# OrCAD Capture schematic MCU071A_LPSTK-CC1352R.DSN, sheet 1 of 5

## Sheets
1 1_RF: size A3; title: LPSTK-CC1352R1; rev: A; company: Texas Instruments
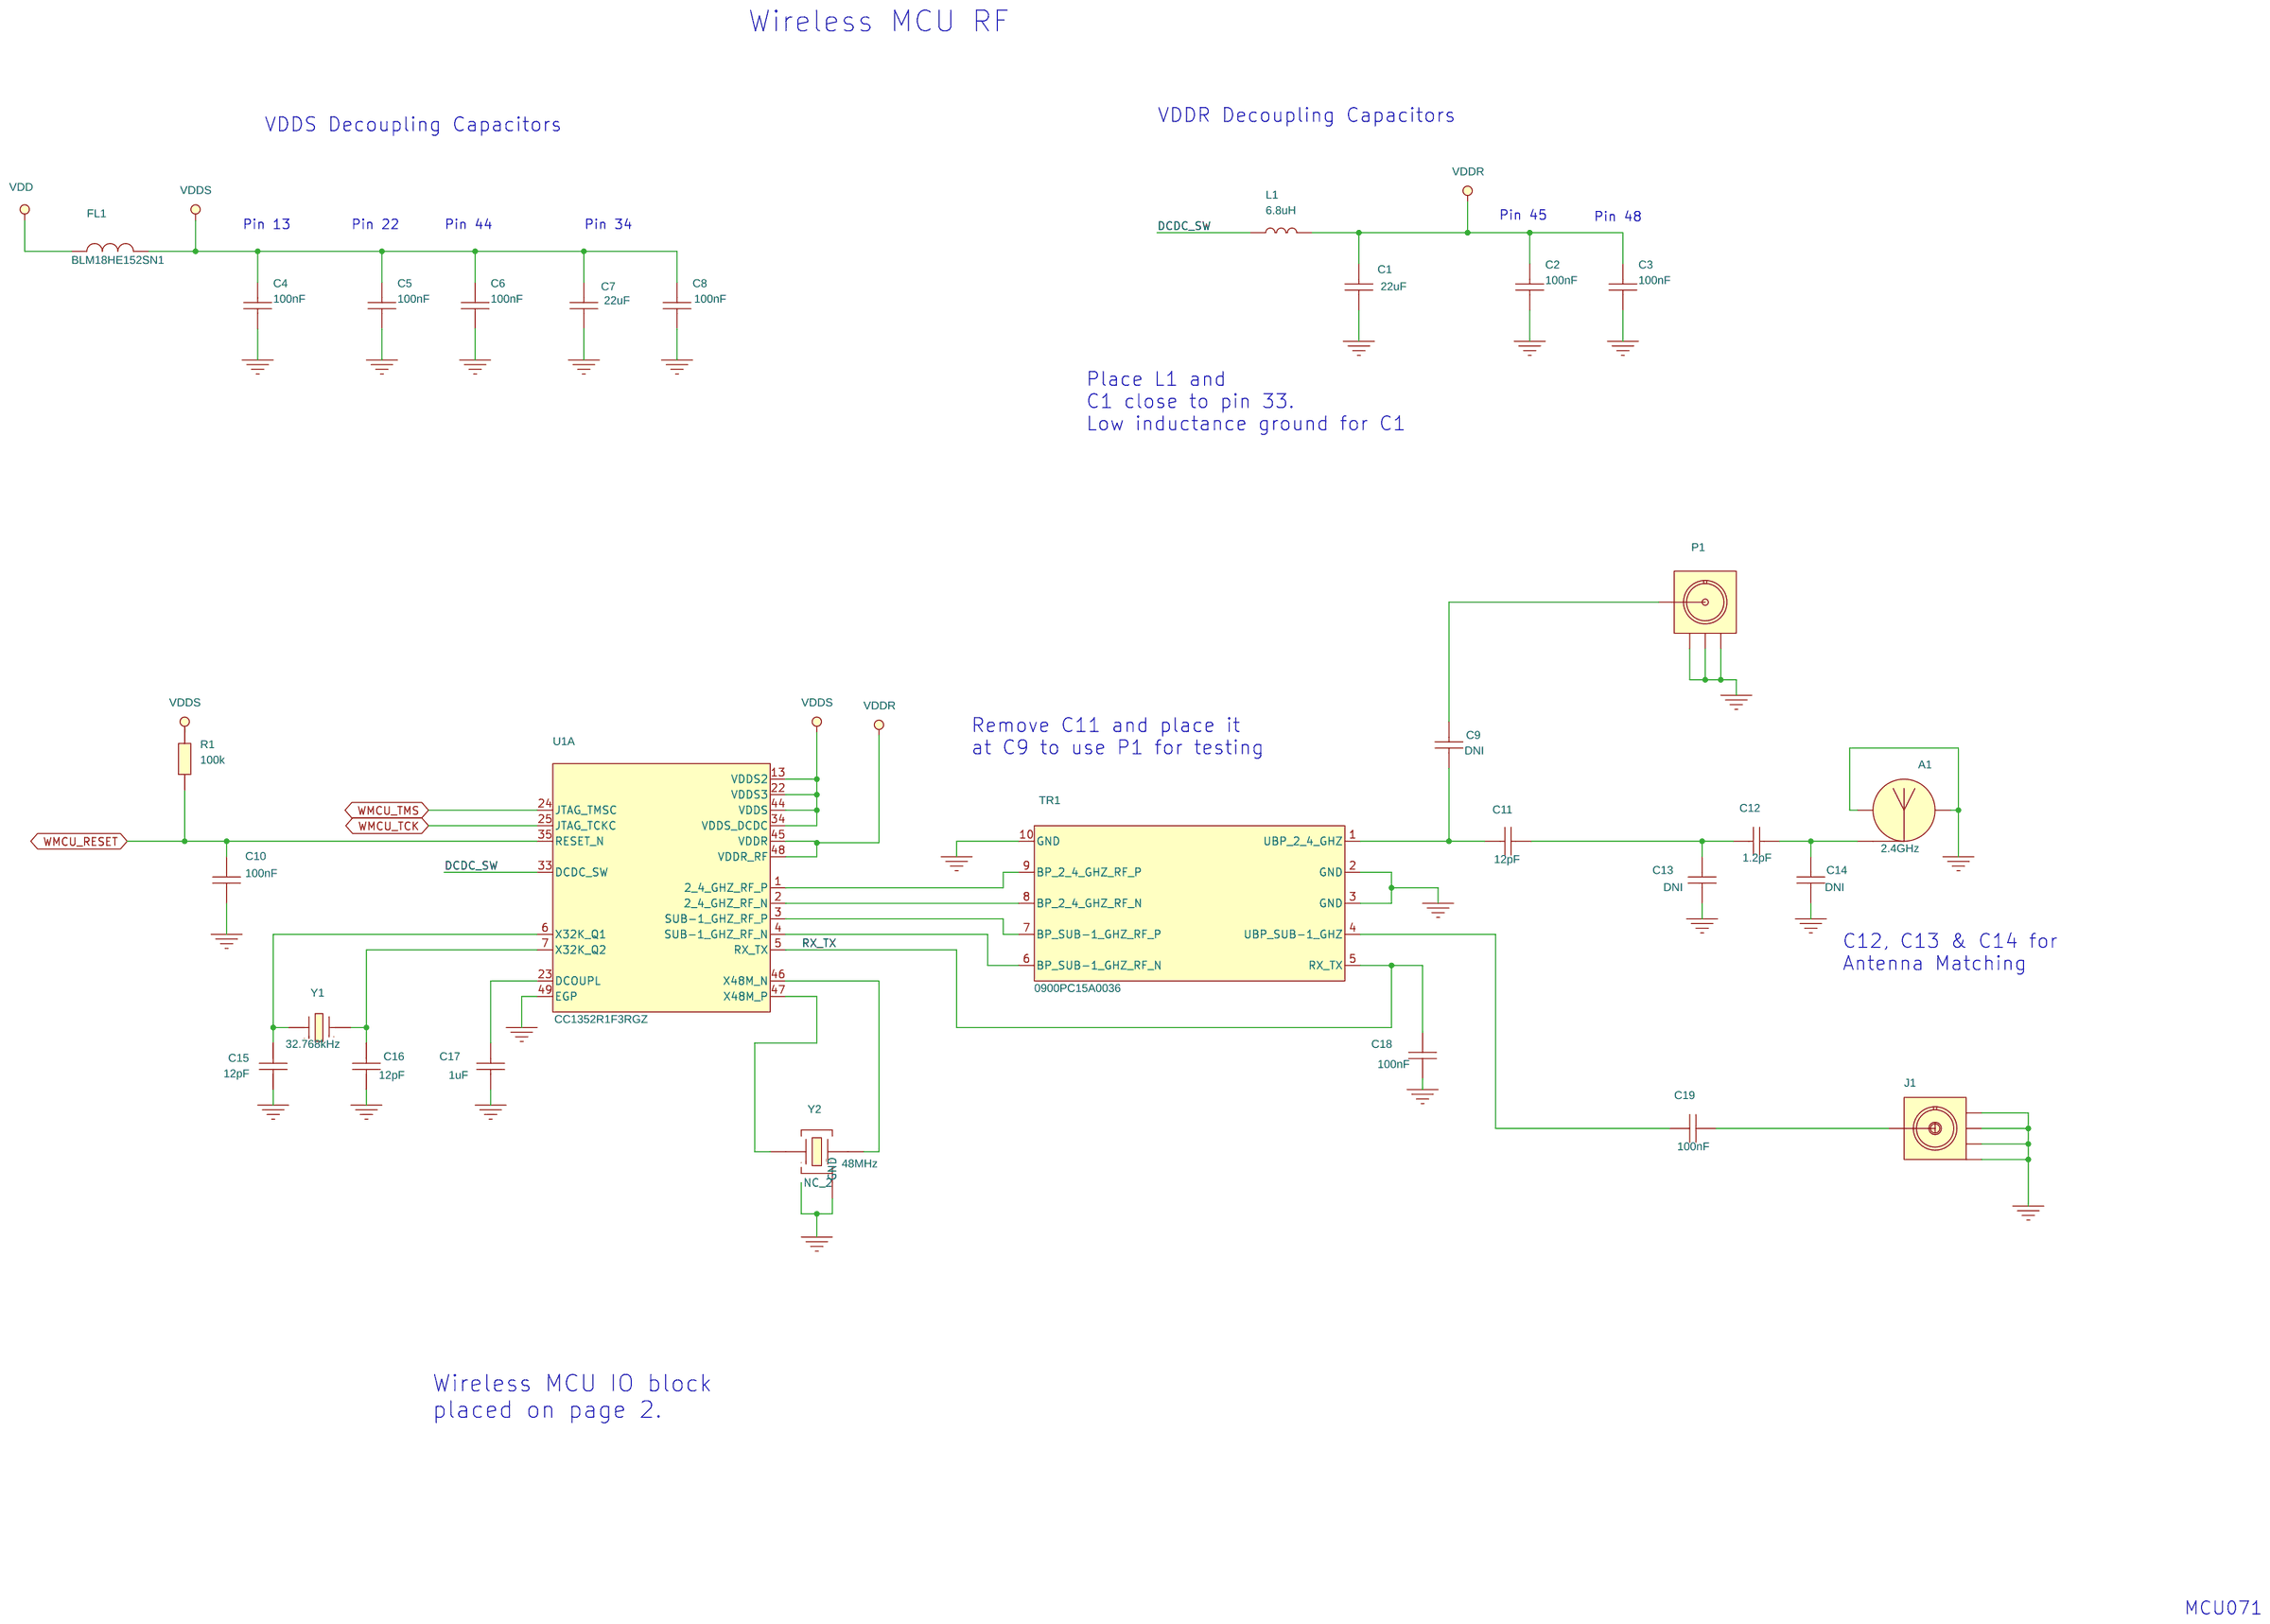
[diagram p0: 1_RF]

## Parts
A1  2.4GHz  [ANTENNA_DN007N]
C1  22uF  [CAPC1608X100A2N]
C2  100nF  [CAPC1005X60A2N]
C3  100nF  [CAPC1005X60A2N]
C4  100nF  [CAPC1005X60A2N]
C5  100nF  [CAPC1005X60A2N]
C6  100nF  [CAPC1005X60A2N]
C7  22uF  [CAPC1608X100A2N]
C8  100nF  [CAPC1005X60A2N]
C9  DNI  [CAPC0603X35B2N]
C10  100nF  [CAPC1005X60A2N]
C11  12pF  [CAPC0603X35B2N]
C12  1.2pF  [CAPC0603X35B2N]
C13  DNI  [CAPC0603X35B2N]
C14  DNI  [CAPC0603X35B2N]
C15  12pF  [CAPC1005X60A2N]
C16  12pF  [CAPC1005X60A2N]
C17  1uF  [CAPC1005X60A2N]
C18  100nF  [CAPC0603X35B2N]
C19  100nF  [CAPC0603X35B2N]
FL1  BLM18HE152SN1  [FIL_BLM18HE152SN1DN]
J1  SLE-100010011  [DONGGUAN_SLE100010011_A2N]
L1  6.8uH  [INDC2012X150A2N]
P1  MM5829-2700  [MURATA_MM58292700RJ4_A2N]
R1  100k  [RESC1005X40B2N]
TR1  0900PC15A0036  [XFMR_IPC1352_A2N]
U1  CC1352R1F3RGZ  [QFNFC50P700X700X100-49A2N]  (sections A,B)
Y1  32.768kHz  [XTAL_FC135_A2N]
Y2  48MHz  [XTAL_XRCMD_A2N]

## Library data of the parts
A1 = ANTENNA_DN007_0: ANTENNA, NON COMPONENT, 2.4GHz INVERTED F ANTENNA, NOT APPLY; Additional Datasheet URL: N/A; CLASS: DISCRETE; Country of Origin: Missing Info; Datasheet URL: www.ti.com; Exclusive for Customers: TEXAS INSTRUMENTS NORWAY; FPLIST: ANTENNA_DN007N,ANTENNA_DN007AN; Mass: N/A; Maximum Operating Temperature: +85DEGC; Minimum Operating Temperature: -40DEGC; Mounting Type: Not Apply; NOTEfied URL: https://notefied-dynamic-precision.com/NOTEfiedWebInterface/part/show?partNumber=13-00347; Notes: Custom Item; Packing Size: N/A; Packing Type: Missing Info; Part Number: 13-00347; Part Type: Mechanic|ANTENNA|NON COMPONENT; ROHS: Not Applicable; Revision: R018; Status: Released; Texas Part Status: Under Review; Type: Mechanic; Vendor: TEXAS INSTRUMENTS; Vendor Part Number: DN007; Vendor Part Status: Active
C1 C7 = CAPACITOR_2: CAPACITOR, CERAMIC, X5R, 22uF, 6.3V, -20%/+20%, -55DEGC/+85DEGC, 0603, SMD; ALT_SYMBOLS: CAPC1608X100A2L,CAPC1608X100A2M; Additional Datasheet URL: https://psearch.en.murata.com/capacitor/product/GRM188R60J226MEA0%23.pdf?graph=b716c79755abcf9781f13c23aa73cc81; AutoDoc File: https://notefied-dynamic-precision.com/DB/Apps/Desktop/Item/Object.aspx?id=104385; BU Name: DYNAMIC PRECISION GDANSK; Budget Currency: EUR; Budget Price: 0.062; Budgetary Price: 0.062 EUR; Client Status: UNDER_REVIEW; Country of Origin: Japan; Datasheet URL: https://search.murata.co.jp/Ceramy/image/img/A01X/G101/ENG/GRM188R60J226MEA0-01A.pdf; Datasheet URL 1: http://psearch.murata.com/capacitor/product/GRM188R60J226MEA0%23.pdf; Datasheet URL 2: http://search.murata.co.jp/Ceramy/image/img/w_hinm/L0005E.pdf; Definied Quality: INDUSTRIAL; Dielectric Type: X5R; Esd Level: N/A; Lead Time: 26; MPN: GRM188R60J106ME47D; MPN Status: NRND; MSL: 1; MTBF: N/A; MTBF Standard: N/A; Manufacturer: MURATA; Mass: 0.0091g; Max Oper Temp: +85DEGC; Max Tol: +20%; Maximum Operating Temperature: +85DEGC; Maximum Tolerance: +20%; Min Oper Temp: -55DEGC; Min Tol: -20%; Minimum Operating Temperature: -55DEGC; Minimum Tolerance: -20%; Mounting Type: SMD; NOTE Status: PREFERRED; NOTEfied URL: https://notefied-dynamic-precision.com/NOTEfiedWebInterface/part/show?partNumber=02-07053; Old Footprint: CAPC1608X90N; PCB Package: 0603; Packing Size: 4000; Packing Type: Tape & Reel; Part Number: 02-07053; Part Type: Capacitor|CERAMIC|0603|STANDARD; REACH/SVHC Compliance: Compliant; REACH/SVHC Details: SVHC List Version Jul 7, 2017; REACH/SVHC Source: REACH Declaration; REACH/SVHC Status: Unaffected; REACH/SVHC_COMPLIANCE: COMPLIANT; REACH/SVHC_DETAILS: SVHC LIST VERSION Dec 17, 2015; REACH/SVHC_SOURCE: REACH DECLARATION; REACH/SVHC_STATUS: UNAFFECTED; ROHS: Compliant; Rated Voltage: 6.3V; Revision: R015; RoHS Status: ROHS_COMPLIANT; Rtd Voltage: 6.3V; Status: Released; Texas Part Status: Under Review; Type: Capacitor; Vendor: MURATA; Vendor Part Number: GRM188R60J226MEA0D; Vendor Part Status: Active; WEIGHT: 0.0091g
C2-C6 C8 C10 = CAPACITOR: CAPACITOR, CERAMIC X5R, 100nF, 10V, -10%+/10%, -55DEGC /+85DEGC, 0402, SMD; ALT_SYMBOLS: CAPC1005X60A2L,CAPC1005X60A2M; Additional Datasheet URL: http://www.avx.com/products/ceramic-capacitors/surface-mount/x5r-dielectric/; Budgetary Price: 0.004 EUR; Country of Origin: China,Czech Republic,El Salvador,Japan,Malaysia,United Kingdom; Datasheet URL: http://datasheets.avx.com/cx5r.pdf; Dielectric Type: X5R; Lead Time: 11; Mass: 0.001g; Maximum Operating Temperature: +85DEGC; Maximum Tolerance: +10%; Minimum Operating Temperature: -55DEGC; Minimum Tolerance: -10%; Mounting Type: SMD; NOTEfied URL: https://notefied-dynamic-precision.com/NOTEfiedWebInterface/part/show?partNumber=02-04065; PCB Package: 0402; Packing Size: 10000; Packing Type: Tape & Reel; Part Number: 02-04065; Part Type: Capacitor|CERAMIC|0402|STANDARD; ROHS: Compliant; Rated Voltage: 10V; Revision: R008; Status: Released; Type: Capacitor; Vendor: AVX; Vendor Part Number: 0402ZD104KAT2A; Vendor Part Status: Active
C9 C13 C14 = CAPACITOR: CAPACITOR, CERAMIC, TBD, 0201, SMD, DNM; ALT_SYMBOLS: CAPC0603X35B2L,CAPC0603X35B2M; Additional Datasheet URL: N/A; Datasheet URL: N/A; Mounting Type: SMD; NOTEfied URL: https://notefied-dynamic-precision.com/NOTEfiedWebInterface/part/show?partNumber=02-01320; PCB Package: 0201; Packing Size: N/A; Packing Type: Tape & Reel; Part Number: 02-01320; Part Type: Capacitor|CERAMIC|0201|STANDARD; ROHS: Compliant; Revision: R006; Status: Released; Type: Capacitor; Vendor: MANUFACTURER SELECTION; Vendor Part Number: CAPACITOR_TBD_0201_DNM; Vendor Part Status: Active
C11 = CAPACITOR: CAPACITOR, CERAMIC C0G/NP0, 12pF, 50V, -5%/+5%, -55DEGC/+125DEGC, 0201, SMD; ALT_SYMBOLS: CAPC0603X35B2L,CAPC0603X35B2M; Additional Datasheet URL: https://psearch.en.murata.com/capacitor/product/GRT0335C1H120JA02%23.pdf; Datasheet URL: https://search.murata.co.jp/Ceramy/image/img/A01X/G101/ENG/GRT0335C1H120JA02-01.pdf; Dielectric Type: C0G/NP0; Mass: 0.00033g; Maximum Operating Temperature: +125DEGC; Maximum Tolerance: +5%; Minimum Operating Temperature: -55DEGC; Minimum Tolerance: -5%; Mounting Type: SMD; NOTEfied URL: https://notefied-dynamic-precision.com/NOTEfiedWebInterface/part/show?partNumber=02-09025; PCB Package: 0201; Packing Size: 15000; Packing Type: Tape & Reel; Part Number: 02-09025; Part Type: Capacitor|CERAMIC|0201|STANDARD; REACH/SVHC Compliance: Compliant; REACH/SVHC Details: SVHC List Version Jun 27, 2018; REACH/SVHC Source: REACH Declaration; REACH/SVHC Status: Unaffected; ROHS: Compliant; Rated Voltage: 50V; Revision: R003; Status: Released; Texas Part Status: Under Review; Type: Capacitor; Vendor: MURATA; Vendor Part Number: GRT0335C1H120JA02D; Vendor Part Status: Active
C12 = CAPACITOR: CAPACITOR, CERAMIC C0G/NP0, 1.2pF, 50V, -0.1pF/+0.1pF, -55DEGC/+125DEGC, 0201, SMD; ALT_SYMBOLS: CAPC0603X35B2L,CAPC0603X35B2M; Additional Datasheet URL: https://psearch.en.murata.com/capacitor/product/GRM0335C1H1R8BA01%23.pdf?graph=38c54ab5c953f76e5ff52d6468a9a582; Budgetary Price: 0.006 EUR; Country of Origin: Missing Info; Datasheet URL: https://search.murata.co.jp/Ceramy/image/img/A01X/G101/ENG/GRM0335C1H1R8BA01-01A.pdf; Dielectric Type: C0G/NP0; Lead Time: 18; Mass: 0.00033g; Maximum Operating Temperature: +125DEGC; Maximum Tolerance: +0.1pF; Minimum Operating Temperature: -55DEGC; Minimum Tolerance: -0.1pF; Mounting Type: SMD; NOTEfied URL: https://notefied-dynamic-precision.com/NOTEfiedWebInterface/part/show?partNumber=02-06132; PCB Package: 0201; Packing Size: 50000; Packing Type: Tape & Reel; Part Number: 02-06132; Part Type: Capacitor|CERAMIC|0201|STANDARD; REACH/SVHC Compliance: Compliant; REACH/SVHC Details: SVHC List Version Jul 7, 2017; REACH/SVHC Source: REACH Declaration; REACH/SVHC Status: Unaffected; ROHS: Compliant; Rated Voltage: 50V; Revision: R017; Status: Released; Texas Part Status: Under Review; Type: Capacitor; Vendor: MURATA; Vendor Part Number: GRM0335C1H1R2BA01D; Vendor Part Status: Active
C15 C16 = CAPACITOR: CAPACITOR, CERAMIC C0G/NP0, 12pF, 50V, -5%/+5%, -55DEGC/+125DEGC, 0402, SMD; ALT_SYMBOLS: CAPC1005X60A2L,CAPC1005X60A2M; Additional Datasheet URL: http://product.tdk.com/info/en/documents/chara_sheet/C1005C0G1H120J050BA.pdf; Budgetary Price: 0.01 EUR; Country of Origin: China,Japan; Datasheet URL: http://product.tdk.com/info/en/catalog/datasheets/mlcc_commercial_general_en.pdf; Dielectric Type: C0G/NP0; Mass: 0.00125g; Maximum Operating Temperature: +125DEGC; Maximum Tolerance: +5%; Minimum Operating Temperature: -55DEGC; Minimum Tolerance: -5%; Mounting Type: SMD; NOTEfied URL: https://notefied-dynamic-precision.com/NOTEfiedWebInterface/part/show?partNumber=02-04953; PCB Package: 0402; Packing Size: 10000; Packing Type: Tape & Reel; Part Number: 02-04953; Part Type: Capacitor|CERAMIC|0402|STANDARD; ROHS: Compliant; Rated Voltage: 50V; Revision: R009; Status: Released; Type: Capacitor; Vendor: Yageo; Vendor Part Number: CC0402JRNPO9BN120; Vendor Part Status: NRND
C17 = CAPACITOR: CAPACITOR, CERAMIC X7R, 1uF, 6.3V, -10%/+10%, -55DEGC/+125DEGC, 0402, SMD; ALT_SYMBOLS: CAPC1005X60A2L,CAPC1005X60A2M; Additional Datasheet URL: http://www.avx.com/products/ceramic-capacitors/surface-mount/x7r-dielectric/; Budgetary Price: 0.129 EUR; Country of Origin: United States; Datasheet URL: http://datasheets.avx.com/X7RDielectric.pdf; Dielectric Type: X7R; Lead Time: 17; Mass: N/A; Maximum Operating Temperature: +125DEGC; Maximum Tolerance: +10%; Minimum Operating Temperature: -55DEGC; Minimum Tolerance: -10%; Mounting Type: SMD; NOTEfied URL: https://notefied-dynamic-precision.com/NOTEfiedWebInterface/part/show?partNumber=02-07897; PCB Package: 0402; Packing Type: Tape & Reel; Part Number: 02-07897; Part Type: Capacitor|CERAMIC|0402|STANDARD; ROHS: Compliant; Rated Voltage: 6.3V; Revision: R018; Status: Released; Type: Capacitor; Vendor: AVX; Vendor Part Number: 04026C105KAT2A; Vendor Part Status: Active
C18 C19 = CAPACITOR: CAPACITOR, CERAMIC X5R, 100nF, 6.3V, -10%/+10%, -55DEGC/+85DEGC, 0201, SMD; ALT_SYMBOLS: CAPC0603X35B2L,CAPC0603X35B2M; Additional Datasheet URL: https://psearch.en.murata.com/capacitor/product/GRM033R60J104KE19%23.pdf?graph=72a39c0f797dd1a834cfa8e96ea9f020; Budgetary Price: 0.008 EUR; Country of Origin: Philippines; Datasheet URL: https://search.murata.co.jp/Ceramy/image/img/A01X/G101/ENG/GRM033R60J104KE19-01A.pdf; Dielectric Type: X5R; Lead Time: 12; Mass: 0.00033g; Maximum Operating Temperature: +85DEGC; Maximum Tolerance: +10%; Minimum Operating Temperature: -55DEGC; Minimum Tolerance: -10%; Mounting Type: SMD; NOTEfied URL: https://notefied-dynamic-precision.com/NOTEfiedWebInterface/part/show?partNumber=02-05431; PCB Package: 0201; Packing Size: 15000; Packing Type: Tape & Reel; Part Number: 02-05431; Part Type: Capacitor|CERAMIC|0201|STANDARD; ROHS: Compliant; Rated Voltage: 6.3V; Revision: R020; Status: Released; Type: Capacitor; Vendor: MURATA; Vendor Part Number: GRM033R60J104KE19D; Vendor Part Status: Active
FL1 = FILTER_2PIN: FILTER, EMI, FERRITE BEAD, 1500@100MHz, -25%/+25%, -55DEGC/+125DEGC, 0603, SMD; ALT_SYMBOLS: FIL_BLM18HE152SN1DL,FIL_BLM18HE152SN1DM; Additional Datasheet URL: https://www.murata.com/en-eu/api/pdfdownloadapi?cate=&partno=BLM18HE152SN1%23; AutoDoc File: http://notefied-dynamic-precision.com/DB/Apps/Desktop/Item/Object.aspx?id=85575; Budget Currency: EUR; Budget Price: 0.085; Budgetary Price: 0.065 EUR; CLASS: IC; Country of Origin: Japan,Singapore,Thailand; Datasheet URL: https://www.murata.com/en-eu/products/productdata/8796741599262/ENFA0004.pdf?1441769419000; Datasheet URL 1: http://search.murata.co.jp/Ceramy/image/img/PDF/ENG/L0110S0101BLM18H.pdf; Datasheet URL 2: http://search.murata.co.jp/Ceramy/image/img/PDF/ENG/L0110S0101BLM18H.pdf; FPLIST: FIL_BLM18HE152SN1DN,FIL_BLM18HE152SN1DL,FIL_BLM18HE152SN1DM; Frequency: 100MHz; Impedance: 1500; Inductance: N/A; Lead Time: 9; MPN: BLM18HE152SN1D; MPN Status: ACTIVE; Manufacturer: MURATA; Mass: 0.006g; Max Oper Temp: +125DEGC; Max Tol: +25%; Maximum Operating Temperature: +125DEGC; Maximum Tolerance: +25%; Min Oper Temp: -55DEGC; Min Tol: -25%; Minimum Operating Temperature: -55DEGC; Minimum Tolerance: -25%; Mounting Type: SMD; NOTE Status: PREFERRED; NOTEfied URL: https://notefied-dynamic-precision.com/NOTEfiedWebInterface/part/show?partNumber=04-00470; PCB Package: 0603; Packing Size: 4000; Packing Type: Tape & Reel; Part Number: 04-00470; Part Type: Filter|EMI|FERRITE BEAD|0603; REACH/SVHC Compliance: Compliant; REACH/SVHC Details: SVHC List Version Jul 7, 2017; REACH/SVHC Source: REACH Declaration; REACH/SVHC Status: Unaffected; ROHS: Compliant; Rated Current: 0.5A; Rated Voltage: N/A; Revision: R014; RoHS Status: ROHS_COMPLIANT; Rtd Current: 0.5A; Status: Released; Texas Part Status: Under Review; Type: Filter; Vendor: MURATA; Vendor Part Number: BLM18HE152SN1D; Vendor Part Status: Active; WEIGHT: 0.006g
J1 = CONN_COAX_1_J_4MH: CONNECTOR, COAX, RF, SMA50, FEMALE, STRAIGHT, 1 PIN, SMD; Additional Datasheet URL: N/A; Datasheet URL: N/A; Exclusive for Customers: TEXAS INSTRUMENTS NORWAY; Maximum Operating Temperature: +85DEGC; Minimum Operating Temperature: -40DEGC; Mounting Type: SMD; NOTEfied URL: https://notefied-dynamic-precision.com/NOTEfiedWebInterface/part/show?partNumber=06-07795; Notes: Custom component; Number of Positions: 1; Part Number: 06-07795; Part Type: Connector|COAX|RF; REACH/SVHC Compliance: Missing Info; REACH/SVHC Details: N/A; REACH/SVHC Source: N/A; REACH/SVHC Status: Missing Info; ROHS: Compliant; Rated Voltage: 170V; Revision: R001; Status: Released; Texas Part Status: Under Review; Type: Connector; Vendor: DONGGUAN CITY SLEING INTELLIGENCE; Vendor Part Status: Active
L1 = INDUCTOR: INDUCTOR, STANDARD, FERRITE CORE, 6.8uH, -20%/+20%, 0.11A, -55DEGC/+125DEGC, 0805, SMD; ALT_SYMBOLS: INDC2012X150A2L,INDC2012X150A2M; Additional Datasheet URL: N/A; AutoDoc File: https://notefied-dynamic-precision.com/DB/Apps/Desktop/Item/Object.aspx?id=102853; BU Name: DYNAMIC PRECISION GDANSK; Budget Currency: EUR; Budget Price: 0.059; Budgetary Price: 0.045 USD; Client Status: UNDER_REVIEW; Core Material: FERRITE; Country of Origin: Missing Info; Datasheet URL: http://product.tdk.com/info/en/catalog/datasheets/inductor_commercial_decoupling_mlz2012_en.pdf; Datasheet URL 1: https://product.tdk.com/info/en/catalog/datasheets/inductor_commercial_decoupling_mlz2012_en.pdf; Datasheet URL 2: N/A; Lead Time: 10; MPN: CKS2125100M-T; MPN Status: ACTIVE; Manufacturer: TAIYO YUDEN; Mass: 0.01g; Max Oper Temp: +125DEGC; Max Tol: +20%; Maximum Operating Temperature: +125DEGC; Maximum Tolerance: +20%; Min Oper Temp: -55DEGC; Min Tol: -20%; Minimum Operating Temperature: -55DEGC; Minimum Tolerance: -20%; Mounting Type: SMD; NOTE Status: PREFERRED; NOTEfied URL: https://notefied-dynamic-precision.com/NOTEfiedWebInterface/part/show?partNumber=03-07266; Old Footprint: INDC2012X150N; PCB Package: 0805; Packing Size: 4000; Packing Type: Tape & Reel; Part Number: 03-07266; Part Type: Inductor|STANDARD|CHIP|0805; REACH/SVHC Compliance: Compliant; REACH/SVHC Details: SVHC List Version Jan 12, 2017; REACH/SVHC Source: REACH Declaration; REACH/SVHC Status: Unaffected; REACH/SVHC_COMPLIANCE: COMPLIANT; REACH/SVHC_DETAILS: SVHC LIST VERSION Dec 17, 2015; REACH/SVHC_SOURCE: REACH DECLARATION; REACH/SVHC_STATUS: UNAFFECTED; ROHS: Compliant; Resistance: 0.25; Revision: R013; RoHS Status: ROHS_COMPLIANT; Rtd Current: 1.1A; Status: Released; Texas Part Status: Under Review; Type: Inductor; Vendor: TDK; Vendor Part Number: MLZ2012N6R8LT000; Vendor Part Status: Active; Weight: 0.01g
P1 = CONN_COAX_1_1_P_2MH_V1: CONNECTOR, COAX, MALE, UP TO 12GHz, 30V, SMD; ALT_SYMBOLS: MURATA_MM58292700RJ4_A2L,MURATA_MM58292700RJ4_A2M; Additional Datasheet URL: N/A; Datasheet URL: http://www.murata.com/en-eu/api/pdfdownloadapi?cate=cgConnectors&partno=MM5829-2700; Maximum Operating Temperature: +85DEGC; Minimum Operating Temperature: -40DEGC; Mounting Type: SMD; NOTEfied URL: https://notefied-dynamic-precision.com/NOTEfiedWebInterface/part/show?partNumber=06-05051; Packing Size: 4000; Packing Type: Tape & Reel; Part Number: 06-05051; Part Type: Connector|COAX|STANDARD; REACH/SVHC Compliance: Compliant; REACH/SVHC Details: SVHC List Version Jul 7, 2017; REACH/SVHC Source: REACH Declaration; REACH/SVHC Status: Unaffected; ROHS: Compliant; Rated Voltage: 30V; Revision: R014; Status: Released; Texas Part Status: Under Review; Type: Connector; Vendor: MURATA; Vendor Part Number: MM5829-2700RJ4; Vendor Part Status: Active
R1 = RESISTOR: RESISTOR, THICK FILM, 100k, -5%/+5%, 0.063W, 50V, -55DEGC/+155DEGC, 0402, SMD; Additional Datasheet URL: N/A; AutoDoc File: https://notefied-dynamic-precision.com/DB/Apps/Desktop/Item/Object.aspx?id=114565; BU Name: TEXAS INSTRUMENTS NORWAY; Budget Currency: EUR; Budget Price: 0.014; Budgetary Price: 0.014 EUR; Client Status: UNDER_REVIEW; Country of Origin: United States; Datasheet URL: http://www.vishay.com/docs/20035/dcrcwe3.pdf; Datasheet URL 1: http://www.vishay.com/docs/20035/dcrcwe3.pdf; Datasheet URL 2: N/A; Definied Quality: INDUSTRIAL; Esd Level: N/A; Exclusive for Customers: TEXAS INSTRUMENTS NORWAY; Lead Time: 18; LifeCycle Status: ACTIVE; MPN: RESISTOR_0402_100k_+/-1%_50V_0.063W_M_+/-100PPM; MPN Status: ACTIVE; MSL: N/A; MTBF: N/A; MTBF Standard: N/A; Manufacturer: MANUFACTURER SELECTION; Mass: 0.00065g; Max Oper Temp: +155DEGC; Max TC: +200PPM/DEGC; Max Tol: +5%; Maximum Operating Temperature: +155DEGC; Maximum Temperature Coefficient: +200PPM/DEGC; Maximum Tolerance: +5%; Min Oper Temp: -55DEGC; Min TC: -200PPM/DEGC; Min Tol: -5%; Minimum Operating Temperature: -55DEGC; Minimum Temperature Coeficient: -200PPM/DEGC; Minimum Tolerance: -5%; Mounting Type: SMD; NOTE Status: PREFERRED; NOTEfied URL: https://notefied-dynamic-precision.com/NOTEfiedWebInterface/part/show?partNumber=01-22492; Notes: Standard item: Duplicate Reason: custom footprint for TEXAS INSTRUMENTS NORWAY.; Old Footprint: RESC1005X40N; PCB Package: 0402; Packing Size: 10000; Packing Type: Tape & Reel; Part Number: 01-22492; Part Type: Resistor|0402|STANDARD; REACH/SVHC Compliance: Compliant; REACH/SVHC Details: SVHC List Version Jun 20, 2016; REACH/SVHC Source: Material Declaration; REACH/SVHC Status: Unaffected; REACH/SVHC_COMPLIANCE: COMPLIANT; REACH/SVHC_DETAILS: SVHC LIST VERSION Jun 20, 2016; REACH/SVHC_SOURCE: MATERIAL DECLARATION; REACH/SVHC_STATUS: UNAFFECTED; ROHS: Exempt; Rated Current: N/A; Rated Power: 0.063W; Rated Voltage: 50V; Resistor Type: THICK FILM; Revision: R013; RoHS Status: ROHS_COMPLIANT; Rtd Current: N/A; Rtd Power: 0.063W; Rtd Voltage: 50V; Status: Released; Texas Part Status: Under Review; Type: Resistor; Vendor: VISHAY; Vendor Part Number: CRCW0402100KJNED; Vendor Part Status: Active; Weight: 0.00065g
TR1 = XFMR_IPC1352: TRANSFORMER, RF, CUSTOM, INTEGRATED BALUN AND FILTER, SMD; Additional Datasheet URL: N/A; Datasheet URL: N/A; Exclusive for Customers: TEXAS INSTRUMENTS NORWAY; Mass: N/A; Maximum Operating Temperature: N/A; Minimum Operating Temperature: N/A; Mounting Type: SMD; NOTEfied URL: https://notefied-dynamic-precision.com/NOTEfiedWebInterface/part/show?partNumber=05-00888; Notes: Prototype component; Packing Size: N/A; Packing Type: Missing Info; Part Number: 05-00888; Part Type: Transformer|RF; REACH/SVHC Compliance: Missing Info; REACH/SVHC Details: N/A; REACH/SVHC Source: N/A; REACH/SVHC Status: Not Affected; ROHS: Compliant; Revision: R012; Status: Released; Texas Part Status: Under Review; Type: Transformer; Vendor: Johanson Technology; Vendor Part Status: Preliminary
U1 = IC_RF_CC1352_QFN48_V1: IC, CUSTOM, CC1352R1F3RGZ, QFN48-EP, SMD; ALT_SYMBOLS: QFNFC50P700X700X100-49A2L,QFNFC50P700X700X100-49A2M; Additional Datasheet URL: http://www.ti.com/lit/ml/mpqf123f/mpqf123f.pdf; Datasheet URL: http://www.ti.com/lit/ds/symlink/cc1352r.pdf; Exclusive for Customers: TEXAS INSTRUMENTS NORWAY; Mass: N/A; Maximum Operating Temperature: N/A; Minimum Operating Temperature: N/A; Mounting Type: SMD; NOTEfied URL: https://notefied-dynamic-precision.com/NOTEfiedWebInterface/part/show?partNumber=18-33499; Notes: Custom item: preliminary.; PCB Package: QFN48-EP; Packing Size: 250; Packing Type: Missing Info; Part Number: 18-33499; Part Type: IC|DIGITAL|WIRELESS|OTHER; REACH/SVHC Compliance: Missing Info; REACH/SVHC Details: N/A; REACH/SVHC Source: N/A; REACH/SVHC Status: Missing Info; ROHS: Missing Info; Rated Voltage: N/A; Revision: R019; Status: Released; Texas Part Status: Under Review; Type: IC; Vendor: TEXAS INSTRUMENTS; Vendor Part Number: CC1352R1F3RGZT; Vendor Part Status: Preliminary
Y1 = CRYSTAL: CRYSTAL, RESONATOR, 32.768kHz, -40DEGC/+85DEGC, SMD; ALT_SYMBOLS: XTAL_FC135_A2L,XTAL_FC135_A2M; Additional Datasheet URL: http://www5.epsondevice.com/en/products/crystal_unit/fc135.html; AutoDoc File: http://notefied-dynamic-precision.com/DB/Apps/Desktop/Item/Object.aspx?id=91966; Budget Currency: USD; Budget Price: 1.25375; Budgetary Price: 0.405 USD; CLASS: IC; Capacitance: 7pF; Country of Origin: Japan; Datasheet URL: https://support.epson.biz/td/api/doc_check.php?dl=brief_FC-135&lang=en; Datasheet URL 1: http://www.eea.epson.com/portal/pls/portal/docs/1/1525528.PDF; Datasheet URL 2: http://www.eea.epson.com/portal/pls/portal/docs/1/1525451.PDF; Definied Quality: INDUSTRIAL; Esd Level: N/A; FPLIST: XTAL_FC-135N,XTAL_FC-135L,XTAL_FC-135M; Lead Time: 10; MPN: FC-135 32.7680KA-AG0; MPN Status: ACTIVE; MSL: N/A; MTBF: N/A; MTBF Standard: N/A; Manufacturer: EPSON; Mass: 0.016g; Max Oper Temp: +85DEGC; Max Tol: +20PPM; Maximum Operating Temperature: +85DEGC; Maximum Stability: N/A; Maximum Tolerance: +20PPM; Min Oper Temp: -40DEGC; Min Tol: -20PPM; Minimum Operating Temperature: -40DEGC; Minimum Stability: N/A; Minimum Tolerance: -20PPM; Mounting Type: SMD; NOTE Status: PREFERRED; NOTEfied URL: https://notefied-dynamic-precision.com/NOTEfiedWebInterface/part/show?partNumber=12-00546; Notes: Q13FC13500002 / This device contains Lead titanium trioxide, CAS No. 12060-00-3, which exceeds the 0.1% SVHC limit.; Old Footprint: XTAL_FC-135N; Packing Size: 1000; Packing Type: Tape & Reel; Part Number: 12-00546; Part Type: Crystal|RESONATOR; REACH/SVHC Compliance: Non-Compliant; REACH/SVHC Details: SVHC List Version Jan 07, 2017; REACH/SVHC Source: REACH Declaration; REACH/SVHC Status: Affected; ROHS: Exempt; Rated Voltage: N/A; Revision: R017; RoHS Status: ROHS_COMPLIANT; Status: Released; Texas Part Status: Under Review; Type: Crystal; Vendor: EPSON; Vendor Part Number: FC-135 32.7680KA-AG0; Vendor Part Status: Active; WEIGHT: N/A
Y2 = XTAL_4_V2: CRYSTAL, RESONATOR, 48MHz, -20PPM/+20PPM, -40DEGC/+85DEGC, SMD; ALT_SYMBOLS: XTAL_XRCMD_A2L,XTAL_XRCMD_A2M; Additional Datasheet URL: N/A; Capacitance: 7pF; Datasheet URL: https://www.murata.com/~/media/webrenewal/support/library/catalog/products/timingdevice/crystalu/p79e.ashx?la=en-us; Exclusive for Customers: TEXAS INSTRUMENTS NORWAY; Maximum Operating Temperature: +85DEGC; Maximum Stability: +20PPM; Maximum Tolerance: +10PPM; Minimum Operating Temperature: -40DEGC; Minimum Stability: -20PPM; Minimum Tolerance: -10PPM; Mounting Type: SMD; NOTEfied URL: https://notefied-dynamic-precision.com/NOTEfiedWebInterface/part/show?partNumber=12-01382; Notes: Custom component; Packing Size: 3000; Packing Type: Tape & Reel; Part Number: 12-01382; Part Type: Crystal|RESONATOR; REACH/SVHC Compliance: Compliant; REACH/SVHC Details: SVHC List Version Jun 27, 2018; REACH/SVHC Source: REACH Declaration; REACH/SVHC Status: Unaffected; ROHS: Compliant; Revision: R005; Status: Released; Texas Part Status: Under Review; Type: Crystal; Vendor: MURATA; Vendor Part Number: XRCMD48M000F1P2AR0; Vendor Part Status: Active

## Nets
GND: A1.2(GND) A1.3(GND) C1.2 C2.2 C3.2 C4.2 C5.2 C6.2 C7.2 C8.2 C10.2 C13.2 C14.2 C15.2 C16.2 C17.2 C18.2 J1.2 J1.3 J1.4 J1.5 P1.2 P1.M1 P1.M2 TR1.2(GND) TR1.3(GND) TR1.10(GND) U1.49(EGP) Y2.2(NC) Y2.4(GND) ; also on sheet 2 3 4
VDD: FL1.2 ; also on sheet 2 3 4
VDDR: C1.1 C2.1 C3.1 L1.2 U1.45(VDDR) U1.48(VDDR_RF)
VDDS: C4.1 C5.1 C6.1 C7.1 C8.1 FL1.1 R1.2 U1.13(VDDS2) U1.22(VDDS3) U1.34(VDDS_DCDC) U1.44(VDDS)
DCDC_SW: L1.1 U1.33(DCDC_SW)
RX_TX: C18.1 TR1.5(RX_TX) U1.5(RX_TX)
WMCU_RESET: C10.1 R1.1 U1.35(RESET_N) ; also on sheet 2
WMCU_TCK: U1.25(JTAG_TCKC) ; also on sheet 2
WMCU_TMS: U1.24(JTAG_TMSC) ; also on sheet 2
N3032269: C11.2 C12.1 C13.1
N3032277: A1.1(FEED) C12.2 C14.1
N3032725: TR1.9(BP_2_4_GHZ_RF_P) U1.1(2_4_GHZ_RF_P)
N3032753: TR1.8(BP_2_4_GHZ_RF_N) U1.2(2_4_GHZ_RF_N)
N3032777: TR1.7(BP_SUB-1_GHZ_RF_P) U1.3(SUB-1_GHZ_RF_P)
N3032785: C15.1 U1.6(X32K_Q1) Y1.1
N3032797: TR1.6(BP_SUB-1_GHZ_RF_N) U1.4(SUB-1_GHZ_RF_N)
N3032823: C16.1 U1.7(X32K_Q2) Y1.2
N3032853: C17.1 U1.23(DCOUPL)
N3032861: U1.46(X48M_N) Y2.3
N3032929: U1.47(X48M_P) Y2.1
N3033151: C19.2 J1.1
N3060472: C9.2 C11.1 TR1.1(UBP_2_4_GHZ)
N3061599: C9.1 P1.1
N3085116: C19.1 TR1.4(UBP_SUB-1_GHZ)

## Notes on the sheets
sheet 1
- Wireless MCU RF
- VDDS Decoupling Capacitors
- VDDR Decoupling Capacitors
- Pin 45
- Pin 13
- Pin 22
- Pin 44
- Pin 34
- Pin 48
- Place L1 and
  C1 close to pin 33.
  Low inductance ground for C1
- Remove C11 and place it
  at C9 to use P1 for testing
- C12, C13 & C14 for
  Antenna Matching
- Wireless MCU IO block
  placed on page 2.
- MCU071
